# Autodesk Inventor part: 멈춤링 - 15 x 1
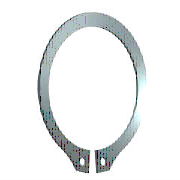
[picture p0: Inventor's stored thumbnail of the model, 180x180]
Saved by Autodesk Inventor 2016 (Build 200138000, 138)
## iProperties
Created: 2015-09
Part Number: 멈춤링 - 15 x 1
Material: 강, 연강
Description: 리테이닝 링(C형)
Document SubType Name: Modeling
Standard: KS B 1336
Designer: mm
Standards Organization: KS
Language: ko-KR
Size Designation: 15 x 1
Categories: <MemberInstance><Categories><Category DisplayName="샤프트 부품" InternalName="7f7aeb1f-a693-4053-b835-cee3144e0d98" Mnemonic="SHFT"><Category DisplayName="써클립" Inter
Density: 1 g/cm^3
Appearance: 광택 - 검은색
IsCustomPart: 1
Author: mduedu
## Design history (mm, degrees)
sketch "스케치1"
  geometry: L1 (-6, 0)-(6, 0) reference; L2 (0, 20.189)-(0, -80.536) reference; L3 (-48.09, 0)-(48.09, 0) reference; L4 (-0.425, -14.637)-(-0.425, -18.137); L5 (-0.425, -6.54)-(-0.425, -13.29); L6 (-2.795, 2.1)-(3.672, 2.1); L7 (0.425, -6.54)-(0.425, -13.29); L8 (0.425, -14.637)-(0.425, -18.137); C1 r 0.85 at (-1.7, -16.283); C2 r 0.85 at (1.7, -16.283); A1 r 7.15 centre (0, -7.5) between (0.425, -14.637) and (-0.425, -14.637); A2 r 9.075 centre (0, -6.975) between (4.291, -14.971) and (-4.291, -14.971); A3 r 10.646 centre (0, -7.5) between (-2.023, -17.952) and (-0.425, -18.137); A4 r 1.7 centre (-1.7, -16.283) between (-3.397, -16.376) and (-2.023, -17.952); A5 r 1.7 centre (-5.095, -16.469) between (-3.397, -16.376) and (-4.291, -14.971); A6 r 1.7 centre (5.095, -16.469) between (4.291, -14.971) and (3.397, -16.376); A7 r 1.7 centre (1.7, -16.283) between (2.023, -17.952) and (3.397, -16.376); A8 r 10.646 centre (0, -7.5) between (0.425, -18.137) and (2.023, -17.952)
  constraints: 16 point on circle, 12 end point, 10 centre point, 9 symmetric about line, 5 point on line, 4 tangent, 3 coincident, 2 horizontal, 1 perpendicular, 1 vertical, 5 other
  dimensions: "d0" = 14.3 diameter of A1 (= ND); "d1" = 3.5 distance of L4.end L4.start (= SRB2); "d6" = 0.425 distance between parallel lines of L2 L5 (= 0.25 x SD5); "d7" = 2.1 distance between parallel lines of L6 L3 (= SRB1); "d8" = 0.525 distance of A1.centre A2.centre (= 0.25 x SRB1); "d9" = 1.7 radius of A4 (= SD5); "d10" = 1.7 radius of A5 (= SD5); "d11" = 1.275 distance from line of L4 A4.centre (= 0.75 x SD5); "d12" = 1.7 diameter of C1 (= SD5); "d13" = 1.7 diameter of C2 (= SD5); "d14" = 7.5 distance from line of A1.centre L1 (= 0.5 x WD)
extrude "본체" new body sketch "스케치1" distance "d2" = 1 (= SD); taper "d3" = 0 deg
workaxis "Work Axis1"
workplane "Work Plane1"
body "Solid1"
other parameters: "WD" = 15 (= WDMIN) [user parameter; used in 1 equation term], "SD" = 1 [user parameter; used in 1 equation term], "SRB1" = 2.1 [user parameter; used in 2 equation terms], "ND" = 14.3 [user parameter; used in 1 equation term], "SRB2" = 3.5 [user parameter; used in 1 equation term], "SD5" = 1.7 [user parameter; used in 6 equation terms], "d15" = 0, "d16" = 0, "d17" = 0, "d41" = 0, "d42" = 0, "WDMIN" = 15 [user parameter; used in 1 equation term], "SD3" = 13.8 [user parameter], "WDMAX" = 16 [user parameter]
